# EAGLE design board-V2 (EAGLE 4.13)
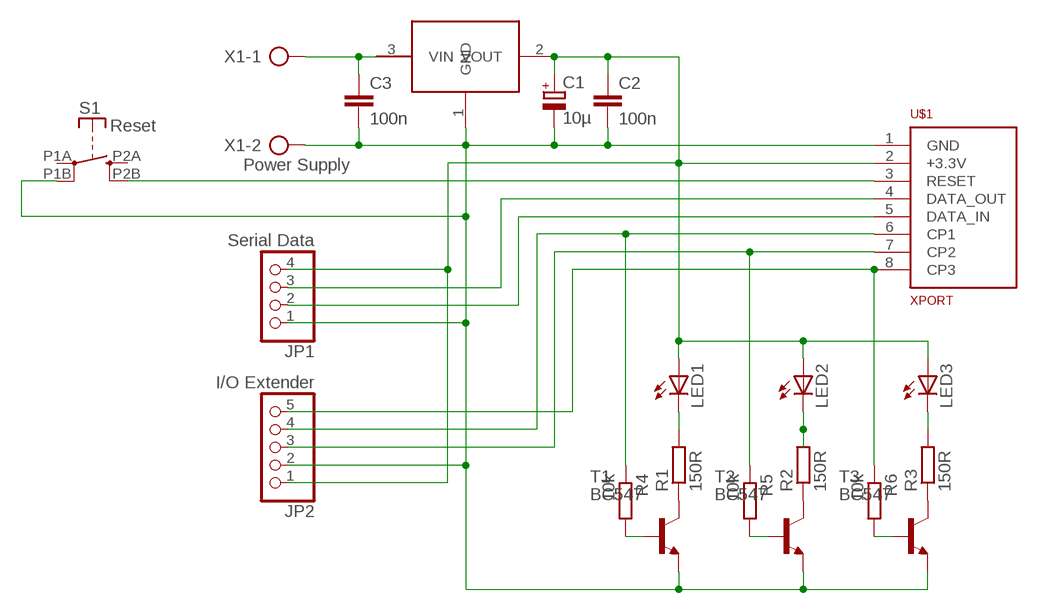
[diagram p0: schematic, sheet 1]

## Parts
C1  10µ  CPOL-EUE2.5-5  [E2,5-5]
C2  100n  C-EU025-024X044  [C025-024X044]
C3  100n  C-EU025-024X044  [C025-024X044]
JP1  Serial Data  PINHD-1X4  [1X04]
JP2  I/O Extender  PINHD-1X5  [1X05]
LED1  LED3MM  [LED3MM]
LED2  LED3MM  [LED3MM]
LED3  LED3MM  [LED3MM]
R1  150R  R-EU_0207/10  [0207/10]
R2  150R  R-EU_0207/10  [0207/10]
R3  150R  R-EU_0207/10  [0207/10]
R4  10k  R-EU_0207/10  [0207/10]
R5  10k  R-EU_0207/10  [0207/10]
R6  10k  R-EU_0207/10  [0207/10]
S1  Reset  KSJ0M410  [KSJ0M410]
T1  BC547  [TO92]
T2  BC547  [TO92]
T3  BC547  [TO92]
U$1  XPORT  [XPORT]
U$2  LD1117V  [TO220V]
X1  Power Supply  AK500/2  [AK500/2]

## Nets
N$1: C1.+ C2.1 JP1.4 JP2.1 LED1.A LED2.A LED3.A U$1.2(+3.3V) U$2.2(VOUT)
N$2: R1.1 T1.3(C)
N$3: S1.P2B(S) U$1.3(RESET)
N$4: JP1.2 U$1.5(DATA_IN)
N$5: JP1.3 U$1.4(DATA_OUT)
N$6: C3.1 U$2.3(VIN) X1.1
N$7: JP2.4 R4.1 U$1.6(CP1)
N$8: JP2.3 R5.1 U$1.7(CP2)
N$9: JP2.5 R6.1 U$1.8(CP3)
N$10: R2.1 T2.3(C)
N$11: C1.- C2.2 C3.2 JP1.1 JP2.2 S1.P1B(P) T1.1(E) T2.1(E) T3.1(E) U$1.1(GND) U$2.1(GND) X1.2
N$12: R3.1 T3.3(C)
N$13: R4.2 T1.2(B)
N$14: R5.2 T2.2(B)
N$15: R6.2 T3.2(B)
N$16: LED1.K(C) R1.2
N$17: LED2.K(C) R2.2
N$18: LED3.K(C) R3.2
Unconnected: S1.P1A(P) S1.P2A(S)

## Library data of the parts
C1 = rcl:CPOL-EU: POLARIZED CAPACITOR, European symbol
C2 C3 = rcl:C-EU: CAPACITOR, European symbol
JP1 = pinhead:PINHD-1X4: PIN HEADER
JP2 = pinhead:PINHD-1X5: PIN HEADER
LED1-LED3 = led:LED: LED
R1-R6 = rcl:R-EU_: RESISTOR, European symbol
S1 = switch-misc:KSJ0M410
T1-T3 = transistor:BC547: NPN TRANSISTOR
U$1 = xport:XPORT
U$2 = st-microelectronics:LD1117
X1 = con-ptr500:AK500/2: CONNECTOR

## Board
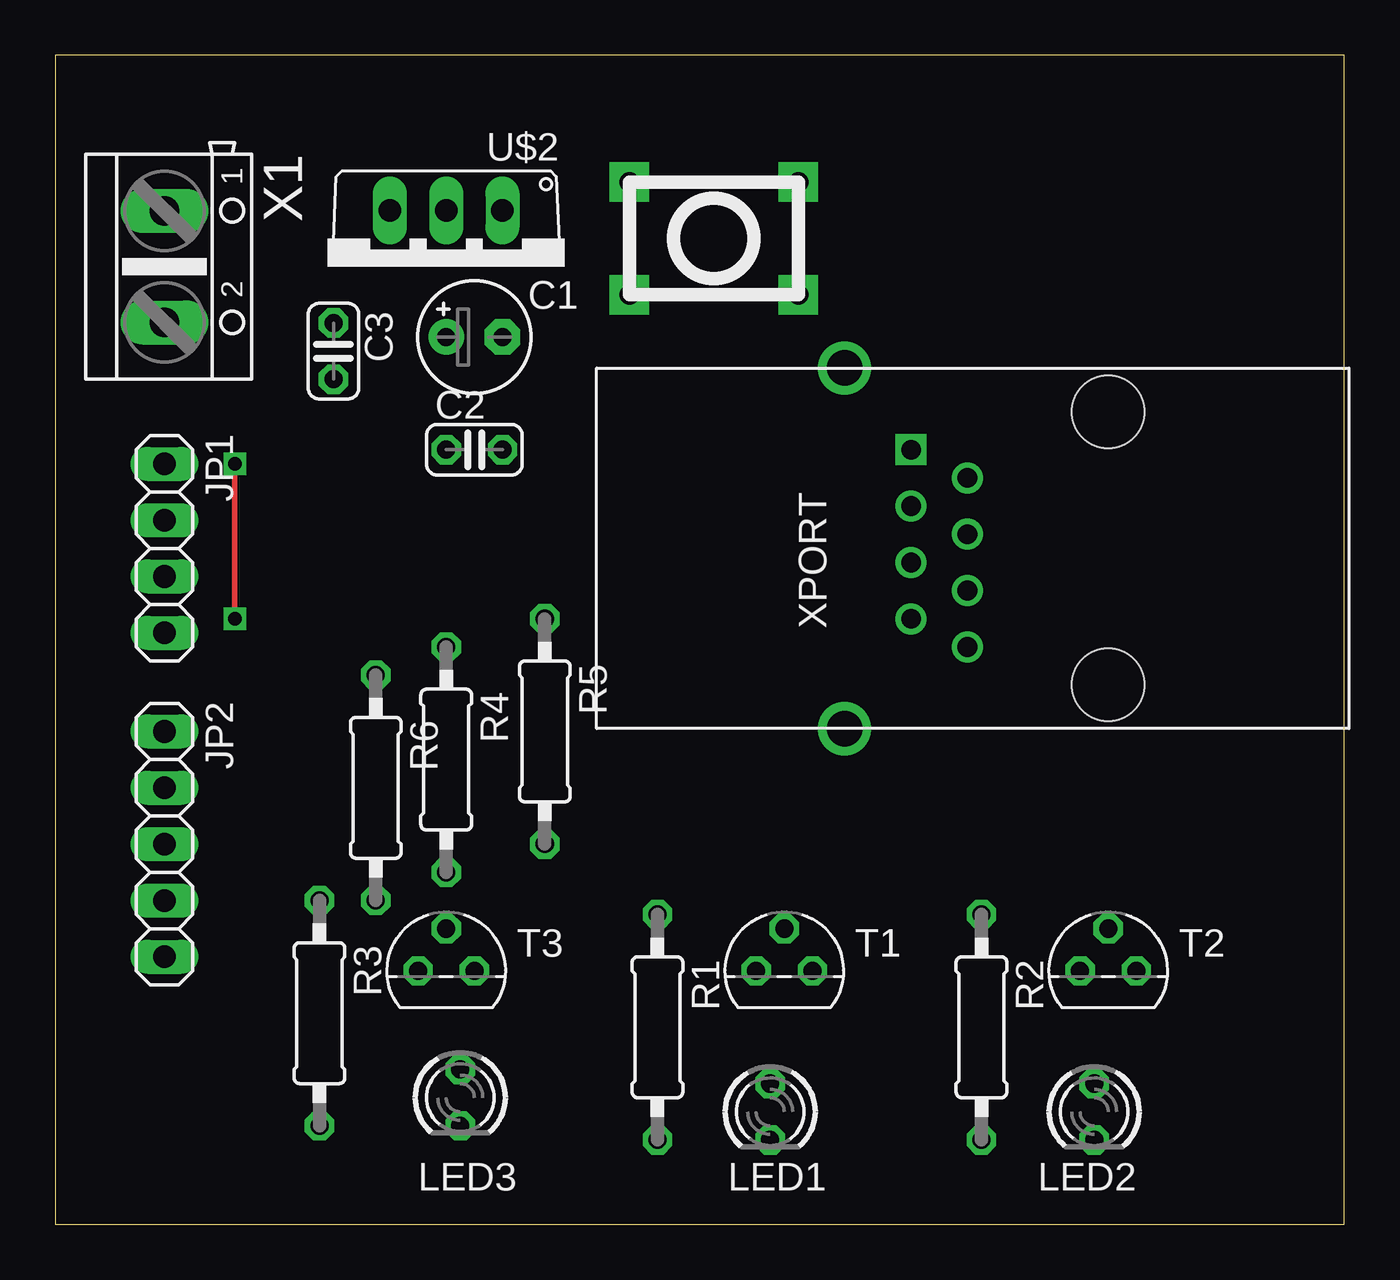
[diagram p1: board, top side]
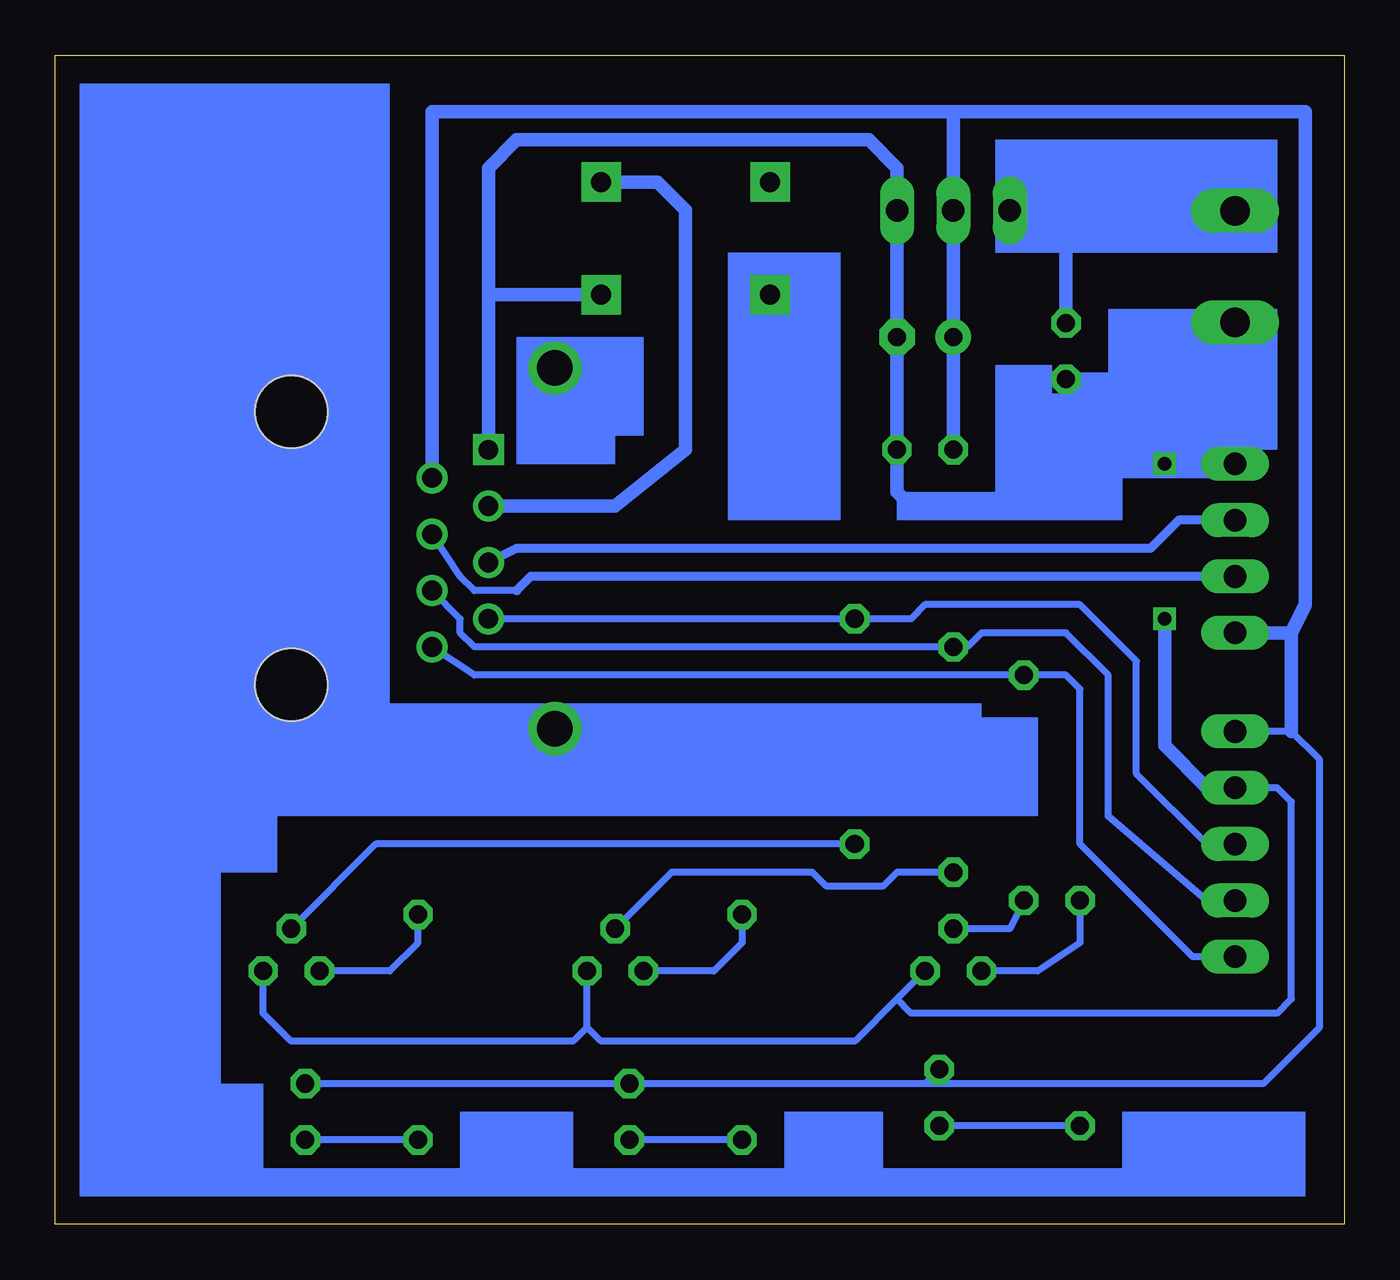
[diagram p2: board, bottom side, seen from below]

Size 58.09 x 52.7 mm. Coordinates in mm from the lower left corner, seen from the top.
Outline: 0,0 58.09,0 58.09,52.7 0,52.7 0,0
Copper layers (1*16): Top 0.035mm / dielectric 1.5mm / Bottom 0.035mm
Design rules "default": minimum track width 10mil, minimum drill 24mil, track to track 8mil, track to pad 8mil, pad to pad 8mil, via to via 8mil, smd to smd 8mil, copper to edge 40mil, drill to drill 8mil, minimum pad ring 10mil, minimum via ring 8mil, stop-mask expansion 4mil, vias tented up to drill 0mil, thermal gap 10mil

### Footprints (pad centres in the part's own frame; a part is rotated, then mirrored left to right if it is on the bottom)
E2,5-5 = drill 0.813 pad 1.6 round: + -1.27,0 | drill 0.813 pad 1.6 octagon: - 1.27,0
C025-024X044 = drill 0.813 octagon: 1 -1.27,0; 2 1.27,0
1X04 = drill 1.016 long: 1 -3.81,0; 2 -1.27,0; 3 1.27,0; 4 3.81,0
1X05 = drill 1.016 long: 1 -5.08,0; 2 -2.54,0; 3 0,0; 4 2.54,0; 5 5.08,0
LED3MM = drill 0.813 octagon: A -1.27,0; K 1.27,0
0207/10 = drill 0.813 octagon: 1 -5.08,0; 2 5.08,0
KSJ0M410 = drill 0.9 pad 1.778 square: P1A -3.81,-2.54; P1B 3.81,-2.54; P2A -3.81,2.54; P2B 3.81,2.54
TO92 = drill 0.813 octagon: 1 1.27,0; 2 0,1.905; 3 -1.27,0
XPORT = drill 0.889 square: 1 -4.445,-8.89 | drill 0.889 round: 2 -3.175,-6.35; 3 -1.905,-8.89; 4 -0.635,-6.35; 5 0.635,-8.89; 6 1.905,-6.35; 7 3.175,-8.89; 8 4.445,-6.35 | drill 1.6 round: P$9 -8.128,-11.887; P$10 8.128,-11.887 | hole 3.251: -6.147,0; 6.147,0
TO220V = drill 1.016 long: 1 -2.54,-2.54; 2 0,-2.54; 3 2.54,-2.54
AK500/2 = drill 1.321 long: 1 -2.515,0; 2 2.515,0

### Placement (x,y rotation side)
C1  18.88,40 0 top
C2  18.88,34.92 0 top
C3  12.54,39.36 270 top
JP1  4.92,30.48 270 top
JP2  4.92,17.14 270 top
LED1  32.22,5.08 270 top
LED2  46.82,5.08 270 top
LED3  18.25,5.71 270 top
R1  27.14,8.88 270 top
R2  41.74,8.88 270 top
R3  11.9,9.52 270 top
R4  17.61,20.95 270 top
R5  22.06,22.22 270 top
R6  14.44,19.68 270 top
S1  29.68,44.45 0 top
T1  32.85,11.42 0 top
T2  47.46,11.42 0 top
T3  17.61,11.42 0 top
U$1  47.46,30.48 270 top
U$2  17.61,43.17 180 top
X1  4.92,43.17 270 top

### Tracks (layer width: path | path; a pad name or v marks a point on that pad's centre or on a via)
N$1
  Bottom 0.305: LED2.A LED1.A 18.88,6.34 | 18.88,6.34 LED3.A | JP2.1 2.38,22.22 1.1,20.95 1.1,8.88 3.64,6.34 18.88,6.34
  Bottom 0.61: 17.61,50.16 41.11,50.16 U$1.2 | 17.61,50.16 U$2.2 C1.+ C2.1 | 17.61,50.16 1.74,50.16 1.74,27.94 2.38,26.67 | 2.38,26.67 JP1.4 | 2.38,22.22 2.38,26.67
N$2
  Bottom 0.305: R1.1 27.14,12.69 28.41,11.42 T1.3
N$3
  Bottom 0.61: S1.P2B 30.95,46.98 29.68,45.71 29.68,34.92 32.85,32.38 U$1.3
N$4
  Bottom 0.406: U$1.5 37.3,30.48 8.73,30.48 7.46,31.75 JP1.2
N$5
  Bottom 0.305: U$1.4 39.84,29.21 39.2,28.57 37.3,28.57
  Bottom 0.406: 37.3,28.57 36.66,29.21 JP1.3 3.64,29.21
N$6
  Bottom 0.61: 12.54,44.45 C3.1 | 12.54,44.45 15.08,44.45 U$2.3 | 12.54,44.45 7.46,44.45 6.18,45.71 X1.1
N$7
  Bottom 0.305: U$1.6 39.84,27.3 39.84,26.67 39.2,26.03 R4.1 16.98,26.03 16.34,26.67 12.54,26.67 10.63,24.76 10.63,18.41 6.18,14.6 JP2.4
N$8
  Bottom 0.305: U$1.7 R5.1 19.52,27.3 18.88,27.94 11.9,27.94 11.27,27.3 9.36,25.39 9.36,20.32 6.18,17.14 JP2.3
N$9
  Bottom 0.305: U$1.8 39.2,24.76 R6.1 12.54,24.76 11.9,24.12 11.9,17.14 6.82,12.06 JP2.5
N$10
  Bottom 0.305: R2.1 41.74,12.69 43.02,11.42 T2.3
N$11  (via drill 0.6)
  Top 0.254: v8.09,27.3 v8.09,34.28
  Bottom 0.305: 20.15,10.15 T3.1 | 20.15,10.15 22.06,8.25 33.49,8.25 34.12,8.88 | 34.12,8.88 T1.1 | 34.12,8.88 34.76,8.25 47.46,8.25 48.73,9.52 T2.1 | JP2.2 3.01,19.68 2.38,19.05 2.38,10.15 3.01,9.52 19.52,9.52 20.15,10.15
  Bottom 0.61: 4.92,38.09 C3.2 12.54,33.65 | 4.92,38.09 JP1.1 | 4.92,38.09 X1.2 | 38.57,41.9 U$1.1 | 38.57,41.9 S1.P1B | 38.57,41.9 38.57,47.62 37.3,48.89 21.42,48.89 20.15,47.62 U$2.1 C1.- C2.2 20.15,33.02 19.52,32.38 13.81,32.38 12.54,33.65 | JP2.2 6.18,19.68 8.09,21.59 v8.09,27.3 | v8.09,34.28 12.54,33.65
N$12
  Bottom 0.305: R3.1 11.9,12.69 13.81,11.42 T3.3
N$13
  Bottom 0.305: R4.2 20.15,15.87 20.79,15.23 23.33,15.23 23.96,15.87 30.31,15.87 T1.2
N$14
  Bottom 0.305: R5.2 43.65,17.14 T2.2
N$15
  Bottom 0.305: R6.2 15.08,13.33 T3.2
N$16
  Bottom 0.305: R1.2 LED1.K
N$17
  Bottom 0.305: R2.2 LED2.K
N$18
  Bottom 0.305: R3.2 LED3.K
(copper drawn outside any net)
  shapes: Bottom area x42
